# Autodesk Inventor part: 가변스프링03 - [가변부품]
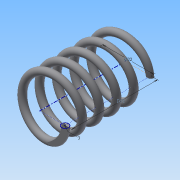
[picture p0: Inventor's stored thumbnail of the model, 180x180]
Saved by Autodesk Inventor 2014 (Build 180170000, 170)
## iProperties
Created: 2015-09
Part Number: 가변스프링03 - [가변부품]
Material: 강철, 탄소
Document SubType Name: Modeling
Designer: study
Density: 7.87 g/cm^3
Appearance: 반연마
Mass: 18.8856 g
Surface Area: 32.5491 cm^2
Volume: 2.3997 cm^3
Author: study
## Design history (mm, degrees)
sketch "스케치1"
  geometry: L1 (0, 0)-(11, 0); L2 (11, 0)-(11, 36.411); L3 (11, 36.411)-(0, 36.411); L4 (0, 36.411)-(0, 0); C1 r 1.5 at (11, 0)
  constraints: 8 end point, 2 parallel, 1 centre point, 1 coincident, 1 horizontal, 1 perpendicular
  dimensions: "d0" = 3 diameter of C1; "d1" = 22 diameter of L2 L4; "d2" = 36.4112 distance of L1.end L2.end (derived)
feature "코일1" pitch "d3" = 10; turns "d5" = 5; dims "d4" = 36.4112 (= d2), "d6" = 0, angle "d7" = 90 deg, angle "d8" = 90 deg, "d9" = 0, "d10" = 0
node "작업 평면1"
sketch "스케치2"
  geometry: L1 (-12.5, 0)-(-9.5, 0) reference; L2 (-12.5, 0)-(-9.5, 0) reference; 1 further point
  constraints: 2 horizontal alignment
extrude "돌출1" cut sketch "스케치2" stored distance "d12" = 10; taper "d13" = 0 deg
node "작업 평면2"
sketch "스케치3"
  geometry: L1 (-9.5, 0)-(-12.5, 0) reference; 1 further point
  constraints: 1 horizontal alignment
extrude "돌출2" cut sketch "스케치3" stored distance "d15" = 10; taper "d16" = 0 deg
node "솔리드1"
node "절단 모서리 투영1"
node "절단 모서리 투영2"
node "절단 모서리 투영3"
other parameters: "d11" = 0, "d14" = 36.4112 (= d2)
